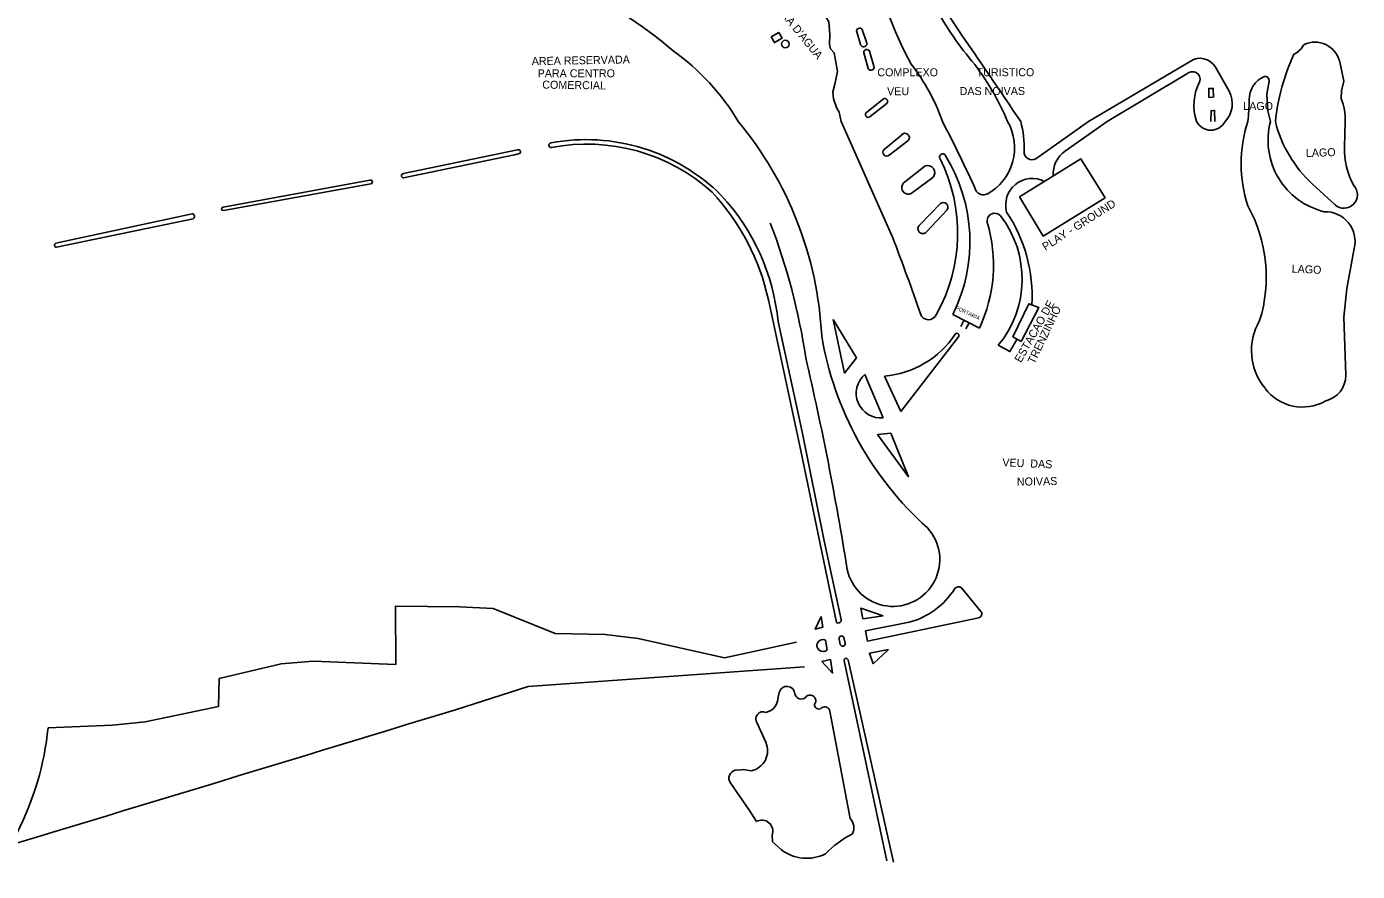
# Model space of a CAD drawing. Extents: x 325899 to 363134, y 7578590 to 7592502.
# Drawn here: x 333008 to 333673, y 7590627 to 7591049 of the extents above; entities that cross this region are included whole.
import ezdxf

# ---------------------------------------------------------------- set-up
doc = ezdxf.new("R2010")
doc.units = 0
for name, color, linetype in [('EDIFEXISTENT', 7, 'Continuous'), ('EDIFIDENTIF', 7, 'Continuous'), ('EDIFOBRAEXIS', 7, 'Continuous')]:
    doc.layers.add(name, color=color, linetype=linetype)

msp = doc.modelspace()

# ---------------------------------------------------------------- linework, layer by layer
at = {"layer": 'EDIFEXISTENT'}
for points in [[(333380.42, 7591044.3), (333384.26, 7591046.46), (333385.88, 7591043.66), (333382.04, 7591041.37), (333380.42, 7591044.3)], [(333504.57, 7590964.28), (333535.26, 7590983.26), (333547.36, 7590963.79), (333516.4, 7590944.7), (333504.57, 7590964.28)], [(333505.35, 7590891.97), (333501.26, 7590894.34), (333509.19, 7590910.84), (333514.16, 7590908.98), (333505.35, 7590891.97)]]:
    msp.add_lwpolyline(points, dxfattribs=at)
msp.add_circle((333387.57, 7591040.65), 1.9, dxfattribs=at)
at = {"layer": 'EDIFOBRAEXIS'}
for points in [[(333415.39, 7591001.91), (333414.42, 7591006.63), (333413.04, 7591009), (333411.63, 7591013.2), (333411.34, 7591016.7), (333412.19, 7591020.52), (333413.53, 7591026.91), (333411.93, 7591036.33), (333410.02, 7591038.32), (333409.63, 7591040.66), (333409.69, 7591045.33), (333409.23, 7591051.77), (333406.75, 7591055.98), (333403.35, 7591059.05), (333398.08, 7591063.5), (333395.51, 7591065.25), (333393.13, 7591069.12), (333390.63, 7591067.16), (333388.9, 7591066.21), (333385.42, 7591065.8), (333381.34, 7591066.01), (333378.97, 7591068.03), (333376.06, 7591071.59)], [(333459.38, 7591072.06), (333465.92, 7591059.68), (333474.02, 7591047.6)], [(333425.11, 7591040.48), (333423.18, 7591046.7)], [(333425.95, 7591047.84), (333428.15, 7591041.6)], [(333428.95, 7591028.41), (333426.68, 7591036.26)], [(333429.54, 7591037.09), (333431.81, 7591029.58)], [(333539.11, 7591001.91), (333591.6, 7591032.97)], [(333664.64, 7591031.7), (333666.62, 7591022.13), (333665.44, 7591017.2), (333665.34, 7591013.37)], [(333548.36, 7591001.91), (333588.2, 7591025.69)], [(333603.15, 7591027.88), (333609.44, 7591017.05)], [(333599.27, 7591013.96), (333599.14, 7591018.47), (333601.39, 7591018.44), (333601.55, 7591014.05)], [(333629.12, 7591021.26), (333628.17, 7591015.67), (333628.74, 7591007.26), (333630, 7591001.91)], [(333428.24, 7591006.59), (333436.42, 7591013.15)], [(333601.55, 7591014.05), (333599.27, 7591013.96)], [(333438.36, 7591011.15), (333429.93, 7591004.4)], [(333600.15, 7591001.91), (333600.29, 7591007.27), (333602.06, 7591007.44), (333602.25, 7591001.91)], [(333415.39, 7591001.91), (333441.18, 7590943.75)], [(333512.74, 7590983.31), (333539.11, 7591001.91)], [(333527.54, 7590987.23), (333548.36, 7591001.91)], [(333667.27, 7591001.91), (333667.02, 7590989.29)], [(333436.92, 7590987.86), (333445.58, 7590995.13)], [(333448.79, 7590992.28), (333439.39, 7590985.11)], [(333252.14, 7590985.23), (333196.66, 7590973.7)], [(333196.7, 7590975.88), (333253.69, 7590987.78)], [(333254.68, 7590985.91), (333252.14, 7590985.23)], [(333447.15, 7590971.62), (333457.3, 7590979.65)], [(333106.45, 7590959.1), (333179.9, 7590972.68)], [(333461.25, 7590973.93), (333451.1, 7590966.42)], [(333180.3, 7590970.73), (333106.67, 7590957.38)], [(333662.27, 7590960.28), (333651.07, 7590970.61), (333651.07, 7590970.61)], [(333454.69, 7590950.28), (333465.01, 7590960.93)], [(333022.91, 7590941.04), (333090.97, 7590955.78)], [(333091.47, 7590953.31), (333023.27, 7590939.05)], [(333468.49, 7590957.83), (333458.08, 7590946.74)], [(333667.75, 7590875.09), (333666.69, 7590904.2), (333668.14, 7590918.52), (333670.23, 7590929.35), (333671.9, 7590938.4)], [(333471.2, 7590905.4), (333484.53, 7590898.65)], [(333383.92, 7590901.92), (333395.86, 7590846.81), (333406.98, 7590792.32), (333415.45, 7590753.09)], [(333423.08, 7590883.81), (333417.03, 7590876.21), (333411.47, 7590903.01)], [(333411.47, 7590903.01), (333423.08, 7590883.81)], [(333476.71, 7590902.53), (333475.19, 7590899.5)], [(333479.38, 7590901.26), (333477.73, 7590898.3)], [(333474.03, 7590894.35), (333445.28, 7590856.98)], [(333493.94, 7590890.06), (333499.79, 7590886.95), (333503.22, 7590892.95)], [(333427.32, 7590875.5), (333436.49, 7590853.82)], [(333445.28, 7590856.98), (333437.01, 7590874.66)], [(333440.18, 7590846.16), (333449, 7590824.4), (333433.56, 7590845.45)], [(333433.56, 7590845.45), (333440.18, 7590846.16)], [(333413.05, 7590751.5), (333395.08, 7590838.19)], [(333475.51, 7590768.88), (333485.3, 7590757.06)], [(333019, 7590698.9), (333051.12, 7590700.17), (333067.59, 7590701.82), (333104.15, 7590709.5), (333104.57, 7590723.51), (333135.44, 7590730.83), (333151.44, 7590732.14), (333192.76, 7590730.57), (333192.65, 7590759.73), (333224.67, 7590759.32), (333241.54, 7590758.52), (333272.5, 7590745.96), (333297.52, 7590745.45), (333313.98, 7590743.5), (333357.14, 7590733.84), (333393.16, 7590741.71)], [(333406.19, 7590749.23), (333402.39, 7590748.27), (333405.39, 7590754.56)], [(333405.39, 7590754.56), (333406.19, 7590749.23)], [(333426.24, 7590753.34), (333425.26, 7590758.74), (333436.5, 7590754.82)], [(333436.5, 7590754.82), (333426.24, 7590753.34)], [(333484.23, 7590753.94), (333428.55, 7590742.24)], [(333428.55, 7590742.24), (333427.63, 7590747.32), (333449.37, 7590751.62)], [(333407.62, 7590742.68), (333408.44, 7590737.91)], [(333414.96, 7590740.61), (333414.35, 7590743.25)], [(333416.81, 7590744.05), (333417.5, 7590741.23)], [(333410.14, 7590732.96), (333411.12, 7590726.24), (333405.81, 7590732)], [(333405.81, 7590732), (333410.14, 7590732.96)], [(333438.24, 7590632.48), (333416.91, 7590732.44)], [(333418.88, 7590732.8), (333441.63, 7590631.71)], [(333431.38, 7590730.81), (333429.53, 7590736.16), (333439.07, 7590738)], [(333439.07, 7590738), (333431.38, 7590730.81)], [(333222.61, 7590707.94), (333258.96, 7590719.46), (333397.07, 7590729.36)], [(333383.89, 7590714.3), (333384.45, 7590716.58)], [(333409.81, 7590707.25), (333419.88, 7590653.6)], [(333377.78, 7590691.65), (333373.49, 7590701.13)], [(333373.03, 7590652.02), (333369.55, 7590657.5), (333359.88, 7590671.49), (333359.28, 7590673.22)], [(333364.4, 7590677.78), (333366.38, 7590678.05), (333370.52, 7590677.39)], [(333385.44, 7590638.01), (333381.09, 7590641.9), (333380.89, 7590645.28)]]:
    msp.add_lwpolyline(points, dxfattribs=at)
for centre, radius, start, end in [((333161, 7590833.65), 265.59, 50.05974, 76.81333), ((333602.18, 7591114.01), 173.19, 189.78995, 208.81621), ((333608.91, 7591139.36), 167.08, 207.72043, 219.94087), ((333424.64, 7591047.09), 1.51, 29.86235, 194.89395), ((330113.57, 7588722.49), 4086.41, 33.9042, 34.67951), ((333426.68, 7591040.91), 1.63, 195.28716, 25.34509), ((333637.14, 7591045.37), 10.82, 295.26528, 331.98756), ((333652.29, 7591028.93), 12.66, 12.63869, 116.21213), ((333261.87, 7590940.7), 119.06, 30.93646, 54.20991), ((333428.19, 7591036.4), 1.52, 27.05339, 185.43967), ((333382.84, 7590953.92), 125.34, 22.51159, 38.58931), ((333594.72, 7591024.4), 9.12, 22.47879, 109.99902), ((333737.09, 7590991.27), 105.12, 155.06981, 174.1901), ((333430.33, 7591029.12), 1.55, 207.16813, 17.13006), ((333370.15, 7590968.16), 101.67, 19.38789, 37.83714), ((333590.98, 7591022.98), 3.88, 346.32265, 135.68408), ((333617.52, 7591010), 25.77, 152.07797, 198.28546), ((333631.58, 7591013.09), 12.22, 111.83308, 181.88686), ((333627.15, 7591022.24), 2.2, 333.45864, 92.88213), ((333437.24, 7591012.01), 1.41, 322.49524, 125.67104), ((333597.83, 7591010.96), 13.11, 316.37383, 27.68686), ((333500.71, 7591014.78), 118.68, 353.77567, 358.99108), ((333641.89, 7591003.52), 25.43, 356.37822, 22.78927), ((333428.94, 7591005.39), 1.39, 120.18873, 315.24799), ((333223.79, 7590885.67), 182.13, 2.89325, 39.66039), ((332910.99, 7590711.01), 626.67, 24.14897, 27.65876), ((333475.69, 7590988.83), 26.41, 298.82063, 29.70354), ((333454.07, 7590988.29), 52.89, 358.62823, 14.92176), ((333600.19, 7591005.64), 8.05, 207.57196, 332.42804), ((333684.12, 7590980.81), 68.75, 162.12252, 197.81148), ((333665.53, 7590992.57), 36.74, 165.26573, 256.38737), ((333693.29, 7591016.81), 62.58, 193.76625, 227.56944), ((333287.84, 7590896.75), 96.13, 45.24298, 100.47939), ((333447.34, 7590993.88), 2.16, 312.17061, 144.69242), ((333254.06, 7590986.78), 1.07, 305.00388, 110.68762), ((333270.54, 7590990.09), 1.21, 98.77523, 274.13948), ((333288.5, 7590897.53), 93.09, 47.89087, 101.07081), ((333438.17, 7590986.49), 1.85, 132.34609, 311.5579), ((333466.19, 7590984.14), 1.58, 35.36362, 216.21153), ((333397.91, 7590941.89), 81.87, 333.53537, 31.82471), ((333510.74, 7590986.58), 3.83, 173.27437, 301.36772), ((333535.32, 7590975.65), 13.94, 123.89555, 183.96313), ((333705.48, 7590988.2), 38.48, 178.37846, 208.41549), ((333458.62, 7590976.34), 3.56, 317.63761, 111.70508), ((333390.8, 7590946.13), 82.87, 330.68935, 26.58177), ((333180.12, 7590971.71), 0.992, 280.24931, 102.69518), ((333196.71, 7590974.79), 1.09, 90.32125, 267.52693), ((333510.86, 7590960.23), 13.21, 62.46091, 195.66778), ((333267.03, 7590888.5), 114.61, 12.22277, 42.94761), ((333448.96, 7590968.9), 3.27, 123.71258, 310.69074), ((333486.48, 7590969.39), 4.17, 208.6555, 297.70376), ((333666.74, 7590965.29), 6.72, 228.31268, 43.1787), ((333106.63, 7590958.25), 0.872, 102.01959, 272.55778), ((333275.64, 7590891.13), 108.81, 5.68779, 42.76246), ((333466.46, 7590959.05), 2.37, 328.7965, 127.67392), ((333554.65, 7590924.17), 73.25, 342.71781, 29.08682), ((333090.96, 7590954.49), 1.29, 293.39112, 89.46532), ((333492.21, 7590952.24), 3.84, 41.56221, 192.63474), ((333453.98, 7590923.14), 51.88, 320.38702, 37.59472), ((333434.91, 7590914.57), 75.96, 356.74985, 33.65353), ((333657.3, 7590941.86), 15, 346.68196, 91.59962), ((333086.71, 7590837.99), 314.35, 8.38682, 21.08659), ((333456.24, 7590948.38), 2.46, 129.14234, 318.35477), ((333416.83, 7590930.23), 74.7, 334.9901, 16.46785), ((333023.27, 7590940.08), 1.03, 110.59713, 269.85131), ((332551.45, 7590597.82), 954.62, 18.81837, 21.24644), ((380087.5, 7600920.35), 47768.53, 192.093154, 192.184643), ((333459.09, 7590907.18), 4.3, 199.52403, 337.77061), ((333650.14, 7590887.45), 29.6, 149.65009, 219.6427), ((333569.55, 7590922.45), 166.17, 189.55472, 228.07196), ((333433.14, 7590921.69), 47.19, 274.69826, 326.46901), ((333473.32, 7590895.07), 1.01, 314.52769, 146.91623), ((331937.68, 7590542.85), 1499.31, 9.02367, 13.146), ((333435.3, 7590866.1), 12.34, 130.32018, 275.54028), ((333654.23, 7590875.34), 13.52, 283.69993, 358.94273), ((333646.01, 7590882.52), 23.31, 216.80431, 299.33503), ((333441.3, 7590782.97), 23.4, 192.25595, 42.63394), ((333439.64, 7590788.65), 38.28, 284.71829, 328.18222), ((333474.05, 7590766.99), 2.39, 52.38492, 141.85979), ((333413.91, 7590752.81), 1.56, 236.86698, 10.31797), ((333483.77, 7590755.84), 1.96, 283.69274, 38.20268), ((333406.28, 7590739.99), 3, 63.49914, 315.93524), ((333415.64, 7590743.47), 1.31, 26.43991, 189.82172), ((333416.21, 7590740.98), 1.31, 196.3504, 10.82963), ((333417.89, 7590732.64), 1.01, 8.85989, 191.76804), ((333388.34, 7590715.61), 4, 3.89487, 166.03124), ((333376.2, 7590714.1), 7.69, 282.25775, 1.49749), ((333395.43, 7590716.39), 3.14, 189.39312, 312.77854), ((333399.89, 7590712.46), 2.84, 323.09366, 144.94627), ((309767.54, 7667444.36), 80241.01, 286.797643, 286.9961682), ((333376.34, 7590703.32), 3.59, 65.42435, 217.49762), ((333404.25, 7590710.4), 2.12, 170.42838, 310.81829), ((333407.27, 7590706.8), 2.58, 10.15768, 129.25508), ((332872.96, 7590713.64), 146.78, 332.76725, 354.23613), ((333368.3, 7590687.49), 10.35, 282.40489, 23.67431), ((333363.62, 7590673.5), 4.35, 79.57249, 183.70114), ((333375.77, 7590647.26), 5.49, 338.83197, 119.91503), ((333415.06, 7590648.89), 6.73, 334.2799, 44.35687), ((333445.24, 7590599.48), 52.37, 117.40775, 135.96186), ((333398.21, 7590654.67), 20.99, 232.52162, 296.51589)]:
    msp.add_arc(centre, radius, start, end, dxfattribs=at)

# ---------------------------------------------------------------- texts
at = {"layer": 'EDIFIDENTIF'}
for s, height, rotation, p in [("CAIXA D'AGUA", 4, 309.2265, (333379.69, 7591061.82)), ('AREA RESERVADA', 4, 1.00301, (333260.78, 7591030.09)), ('PARA CENTRO', 4, 0.00434, (333263.72, 7591024.01)), ('COMPLEXO             TURISTICO', 4, 0.0241, (333433.51, 7591024.52)), ('COMERCIAL', 4, 359.2303, (333266.02, 7591018.37)), ('VEU                 DAS NOIVAS', 4, 0.10271, (333438.38, 7591015.07)), ('LAGO', 4, 359.94696, (333616.42, 7591007.67)), ('LAGO', 4, 2.13016, (333647.78, 7590984.13)), ('PLAY - GROUND', 4, 32.43685, (333517.5, 7590937.24)), ('LAGO', 4, 357.28383, (333640.54, 7590926.44)), ('ESTACAO DE', 4, 60.48799, (333505.28, 7590881.08)), ('PORTARIA', 1.872, 334.71728, (333472.35, 7590908.22)), ('TRENZINHO', 4, 64.28436, (333511.99, 7590880.44)), ('VEU  DAS', 4, 357.58905, (333495.93, 7590829.62)), ('NOIVAS', 4, 1.10461, (333503.29, 7590819.88))]:
    msp.add_text(s, height=height, rotation=rotation, dxfattribs=at).set_placement(p)

doc.saveas('drawing.dxf')
